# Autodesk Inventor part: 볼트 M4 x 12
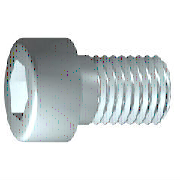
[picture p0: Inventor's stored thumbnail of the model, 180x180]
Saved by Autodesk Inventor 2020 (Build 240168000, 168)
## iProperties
Created: 2016-05
Part Number: 볼트 M4 x 12
Material: 강, 연강
Description: 6각머리 태핑 나사
Document SubType Name: Modeling
Standard: KS B 1003
Designer: mduedu
Standards Organization: KS
Language: ko-KR
Size Designation: M 4 x 12
Categories: <MemberInstance><Categories><Category DisplayName="조임쇠" InternalName="e4da775c-781d-43d5-af7c-5136215cf5a6" Mnemonic="FSTN"><Category DisplayName="볼트" InternalN
Density: 1 g/cm^3
Appearance: 연마 - 진회색
IsCustomPart: 0
Author: mduedu
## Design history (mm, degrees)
sketch "스케치1"
  geometry: L1 (-1, 0)-(12, 0); L2 (12, 0)-(12, 2); L3 (12, 2)-(1.75, 2); L4 (1.75, 2)-(1.32, 2); L5 (1.32, 2)-(0, 2); L6 (0, 2)-(0, 3.5); L7 (0, 3.5)-(-4, 3.5); L8 (-4, 3.5)-(-4, 1.732); L9 (-4, 1.732)-(-2, 1.732); L10 (-2, 1.732)-(-1, 0); L11 (-7.2, 0)-(15.2, 0) reference; L12 (0, -0.7)-(0, 4.2) reference; L13 (1.75, 2)-(0, 2)
  constraints: 22 end point, 6 parallel, 2 collinear, 2 perpendicular, 1 horizontal, 1 point on line
  dimensions: "d1" = 10.25 distance from line of L3.end L2 (= GEL); "d2" = 0.42952 distance of L4.end L3.end (computed from GAL); "d3" = 4 distance between parallel lines of L8 L6 (= KOH); "d4" = 2 distance of L8.end L9.end (= INTI); "d5" = 60 deg angle of L10 L1; "d6" = 4 diameter of L3 L1 (= GD); "d7" = 4 diameter of L5 L1 (= BDM); "d8" = 3.4641 diameter of L9 L1 (= 1.1547 x SW); "d9" = 7 diameter of L7 L1 (= KOD); "d26" = 12 distance between parallel lines of L12 L2 (= NLG)
revolve "본체" sketch "스케치1" stored, may be unused: angle "d10" = 90 deg
sketch "스케치2"
  geometry: L1 (0, -4.9)-(0, 4.9) reference; L2 (-4.9, 0)-(4.9, 0) reference; L3 (1.732, 0)-(0.866, -1.5); L4 (0.866, -1.5)-(-0.866, -1.5); L5 (-0.866, -1.5)-(-1.732, 0); L6 (-1.732, 0)-(-0.866, 1.5); L7 (-0.866, 1.5)-(0.866, 1.5); L8 (0.866, 1.5)-(1.732, 0); 2 further points
  constraints: 12 end point, 1 coincident, 1 horizontal alignment, 1 point on line, 12 other
extrude "슬롯" join sketch "스케치2" stored distance "d11" = 10; taper "d12" = 0 deg
workplane "Work Plane1"
fillet "Fillet2" dims "d30" = 0.1 (= R)
body "Solid1"
fillet "모깎기1" dims "d17" = 0.4 (= RR)
feature "스레드" dims "d13" = 10.25 (= GEL), "d14" = 0
chamfer "모따기1" distance "d15" = 0.42941 (= -0.5 x SPD + 0.5 x GD); stored, may be unused: second distance "d16" = 0.42941 (= GUL), angle "d27" = 45 deg
other parameters: "GD" = 4 (= NND) [user parameter; used in 2 equation terms], "NLG" = 12 [user parameter; used in 1 equation term], "GEL" = 10.25 [user parameter; used in 2 equation terms], "KOD" = 7 [user parameter; used in 1 equation term], "KOH" = 4 [user parameter; used in 1 equation term], "INTI" = 2 [user parameter; used in 1 equation term], "GAL" = 0.42941 (= 0.61345 x PTC) [user parameter; used in 1 equation term], "GUL" = 0.42941 (= 0.61345 x PTC) [user parameter; used in 1 equation term], "BDM" = 4 (= NND) [user parameter; used in 1 equation term], "SW" = 3 [user parameter; used in 2 equation terms], "RR" = 0.4 [user parameter; used in 1 equation term], "SPD" = 3.14117 (= NND - 1.2269 x PTC) [user parameter; used in 1 equation term], "d19" = 0, "d28" = 0, "d29" = 0, "R" = 0.1 [user parameter; used in 1 equation term], "PHH" = 0.2 [user parameter], "GD1" = 3.14117 (= THREADDIA - 1.2269 x PTC) [user parameter], "THREADDIA" = 4 [user parameter; used in 1 equation term], "FAWI" = 45 deg [user parameter], "TPU" = 14.28571 (computed from PTC) [user parameter], "PTC" = 0.7 [user parameter; used in 5 equation terms], "NND" = 4 [user parameter; used in 3 equation terms], "TOA" = 30 deg [user parameter], "E0" = 3.465 (= 1.155 x SW) [user parameter]
